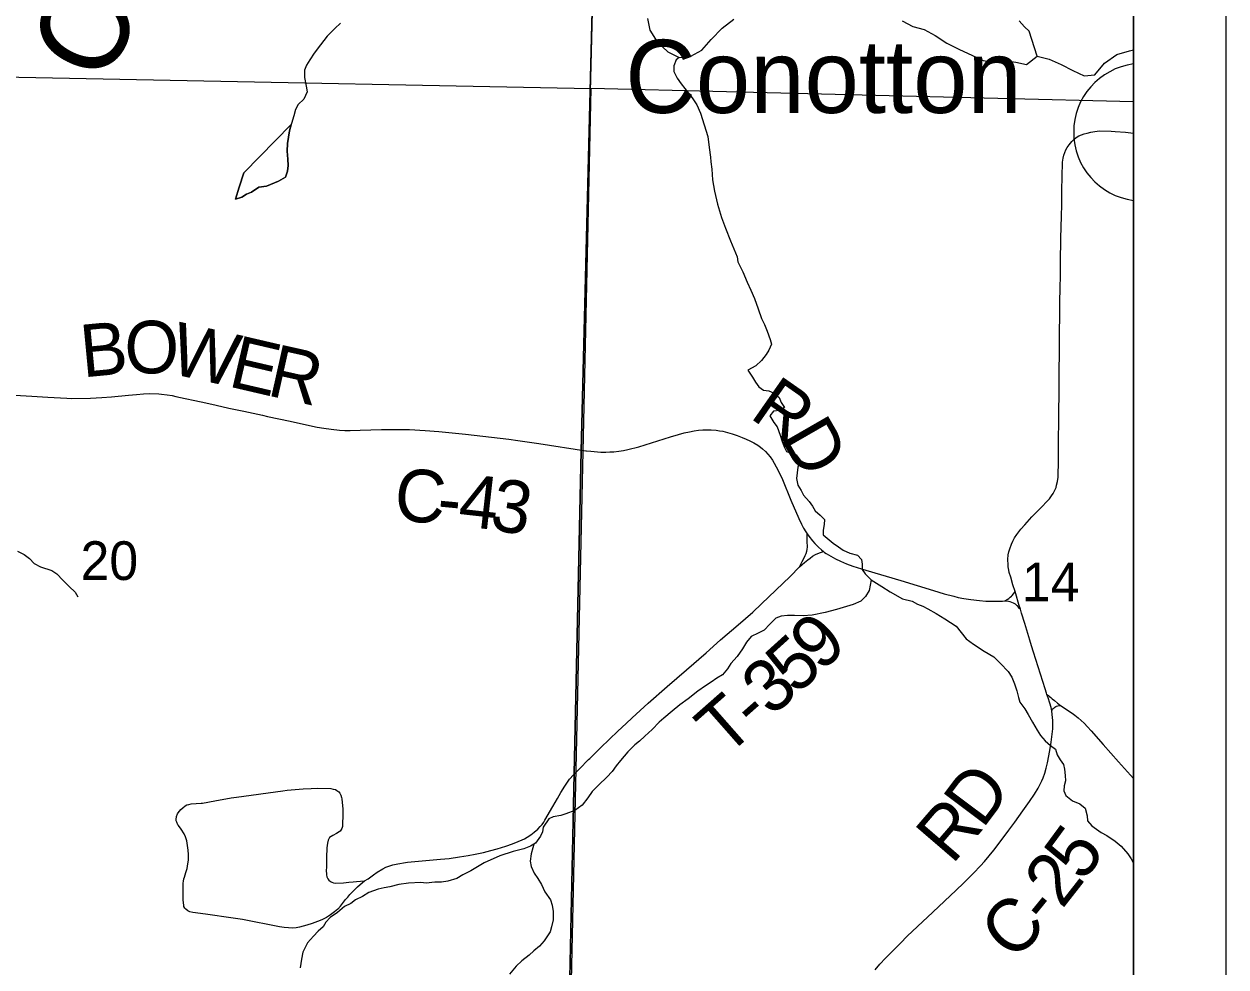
# Model space of a CAD drawing. Extents: x -1.2 to 34, y -8.5 to 22.
# Drawn here: x 7.701 to 9, y 15.729 to 16.749 of the extents above; entities that cross this region are included whole.
import ezdxf

# ---------------------------------------------------------------- set-up
doc = ezdxf.new("R2010")
doc.units = 0
for name, color, linetype in [('GM_X_City_Street', 7, 'Continuous'), ('GM_X_County_Road', 7, 'Continuous'), ('GM_X_County_Road_Text', 7, 'Continuous'), ('GM_X_Major_River', 7, 'Continuous'), ('GM_X_Major_River_Text', 7, 'Continuous'), ('GM_X_Minor_River', 7, 'Continuous'), ('GM_X_Section', 7, 'Continuous'), ('GM_X_Section_Text', 7, 'Continuous'), ('GM_X_Township_Road', 7, 'Continuous'), ('GM_X_Township_Road_Text', 7, 'Continuous'), ('GM_X_Unincorporated_Text', 7, 'Continuous'), ('SH_Cut_Line', 7, 'Continuous'), ('SH_Data', 7, 'Continuous')]:
    doc.layers.add(name, color=color, linetype=linetype)

msp = doc.modelspace()

# ---------------------------------------------------------------- linework, layer by layer
at = {"layer": 'GM_X_City_Street'}
msp.add_line((8.9, 16.5579), (8.9, 16.7054), dxfattribs=at)
msp.add_arc((8.9098, 16.6316), 0.0744, 97.5674, 262.4326, dxfattribs=at)
at = {"layer": 'GM_X_County_Road'}
for points in [[(8.7778, 16.1158), (8.7762, 16.1209), (8.7727, 16.1325), (8.772, 16.135), (8.7697, 16.1424), (8.7673, 16.1505), (8.7658, 16.1556), (8.7652, 16.1582), (8.7646, 16.1616), (8.7644, 16.1639), (8.7642, 16.1697), (8.7646, 16.1748), (8.7652, 16.178), (8.7662, 16.1813), (8.7682, 16.1861), (8.7697, 16.1895), (8.7716, 16.193), (8.774, 16.1966), (8.7783, 16.2026), (8.7826, 16.2072), (8.79, 16.2158), (8.7951, 16.2209), (8.8014, 16.227), (8.806, 16.232), (8.8091, 16.2352), (8.8115, 16.2385), (8.8131, 16.2409), (8.8148, 16.2439), (8.8164, 16.2475), (8.817, 16.25), (8.818, 16.2541), (8.8185, 16.2587), (8.8187, 16.2645), (8.8189, 16.2712), (8.819, 16.3012), (8.8193, 16.3172), (8.8194, 16.3236), (8.8195, 16.3338), (8.8196, 16.3445), (8.8197, 16.3555), (8.8198, 16.3791), (8.82, 16.3872), (8.8201, 16.3992), (8.8202, 16.4178), (8.8203, 16.4304), (8.8206, 16.4507), (8.8208, 16.4603), (8.821, 16.4792), (8.8211, 16.4907), (8.8215, 16.5171), (8.8222, 16.5407), (8.8225, 16.553), (8.8227, 16.5689), (8.8229, 16.5833), (8.8234, 16.5991), (8.8239, 16.6035), (8.8249, 16.6067), (8.8259, 16.6097), (8.827, 16.6125), (8.8285, 16.615), (8.8306, 16.618), (8.8335, 16.6216), (8.8355, 16.6237), (8.838, 16.6258), (8.8409, 16.6275), (8.8437, 16.6288), (8.8469, 16.6298), (8.85, 16.6306), (8.8541, 16.6316), (8.8584, 16.6323), (8.8634, 16.6329), (8.8759, 16.6327), (8.8804, 16.6325), (8.8915, 16.6317), (8.9, 16.6307)], [(7.6908, 16.3472), (7.7094, 16.3463), (7.7266, 16.3453), (7.7469, 16.344), (7.7526, 16.3438), (7.7728, 16.344), (7.7848, 16.3447), (7.7955, 16.3455), (7.8137, 16.3472), (7.8223, 16.3481), (7.8301, 16.3487), (7.8364, 16.349), (7.8465, 16.3488), (7.8495, 16.3485), (7.8554, 16.3478), (7.8608, 16.3468), (7.8649, 16.346), (7.8751, 16.3438), (7.8853, 16.3416), (7.8973, 16.3389), (7.9085, 16.3365), (7.9223, 16.3334), (7.9383, 16.33), (7.9586, 16.3256), (7.9639, 16.3244), (7.9884, 16.3191), (8.0092, 16.3145), (8.0175, 16.3128), (8.0248, 16.3115), (8.0329, 16.3104), (8.0418, 16.3095), (8.0475, 16.3091), (8.0533, 16.309), (8.0643, 16.3093), (8.0757, 16.3097), (8.0872, 16.3101), (8.0969, 16.3103), (8.1084, 16.3103), (8.1174, 16.3101), (8.1344, 16.3091), (8.149, 16.308), (8.1637, 16.3066), (8.1781, 16.3051), (8.2248, 16.2997), (8.2344, 16.2984), (8.2571, 16.295), (8.3079, 16.2872), (8.3088, 16.2871)], [(8.3088, 16.2871), (8.3133, 16.2866), (8.3242, 16.2858), (8.3297, 16.2857), (8.334, 16.2859), (8.3385, 16.2862), (8.3439, 16.2867), (8.3487, 16.2876), (8.3534, 16.2887), (8.3652, 16.2915), (8.3792, 16.2956), (8.3997, 16.3023), (8.4084, 16.3049), (8.4145, 16.3065), (8.42, 16.3078), (8.4253, 16.3086), (8.4298, 16.3093), (8.4345, 16.3097), (8.4391, 16.31), (8.4435, 16.3098), (8.4488, 16.3094), (8.4526, 16.3088), (8.4563, 16.3083), (8.4611, 16.3071), (8.4664, 16.3055), (8.4717, 16.3036), (8.4769, 16.3017), (8.4815, 16.2997), (8.4854, 16.2978), (8.4898, 16.2956), (8.4939, 16.2932), (8.4969, 16.291), (8.4989, 16.2893), (8.5021, 16.2865), (8.5049, 16.2835), (8.5074, 16.2805), (8.5097, 16.2772), (8.5117, 16.2739), (8.516, 16.266), (8.5206, 16.2561), (8.5298, 16.2339), (8.5383, 16.2138), (8.5411, 16.2078), (8.5433, 16.2036), (8.5459, 16.1995), (8.5473, 16.1975), (8.5491, 16.1949), (8.5532, 16.1897), (8.5557, 16.1868), (8.5594, 16.183), (8.5628, 16.18), (8.5649, 16.1783), (8.5661, 16.1774), (8.5679, 16.1762), (8.5729, 16.1732), (8.5778, 16.1703), (8.5835, 16.1677), (8.59, 16.165), (8.5968, 16.1626), (8.6107, 16.1581), (8.6485, 16.1469), (8.6839, 16.1361), (8.6955, 16.1326), (8.7057, 16.1299), (8.7107, 16.1287), (8.7168, 16.1276), (8.7243, 16.1264), (8.7335, 16.1253), (8.7406, 16.1247), (8.7479, 16.1245), (8.7539, 16.1246), (8.7586, 16.1247), (8.7611, 16.1248)], [(8.7611, 16.1248), (8.7635, 16.1264), (8.7652, 16.1276), (8.7668, 16.1288), (8.7681, 16.13), (8.7689, 16.1309), (8.7702, 16.1324), (8.7713, 16.1341), (8.772, 16.135)], [(8.7611, 16.1248), (8.7648, 16.1246), (8.7662, 16.1244), (8.7683, 16.1237), (8.77, 16.1229), (8.772, 16.1216), (8.7739, 16.1199), (8.7758, 16.1179), (8.7778, 16.1158)], [(8.8065, 16.0238), (8.8061, 16.025), (8.8045, 16.0297), (8.7994, 16.0456), (8.7921, 16.0694), (8.7899, 16.0765), (8.788, 16.0826), (8.7849, 16.0931), (8.7826, 16.1004), (8.7791, 16.1118), (8.7778, 16.1158)], [(8.6208, 15.7262), (8.6259, 15.7321), (8.6319, 15.7386), (8.6394, 15.7461), (8.6483, 15.755), (8.6555, 15.7623), (8.6664, 15.7728), (8.6833, 15.7885), (8.7083, 15.8122), (8.7164, 15.8196), (8.727, 15.8305), (8.7348, 15.8386), (8.7389, 15.8432), (8.7491, 15.8555), (8.7526, 15.86), (8.7652, 15.8769), (8.7717, 15.8858), (8.7805, 15.8978), (8.7878, 15.9082), (8.7929, 15.9159), (8.7969, 15.9223), (8.7986, 15.9254), (8.8011, 15.9304), (8.8025, 15.9338), (8.8042, 15.9388), (8.8057, 15.944), (8.807, 15.9498), (8.8095, 15.9632), (8.8109, 15.9722), (8.8128, 15.9867), (8.813, 15.9895), (8.8128, 15.9955), (8.8121, 16.002), (8.8116, 16.0061), (8.8109, 16.0095), (8.8096, 16.0143), (8.8078, 16.0202), (8.8065, 16.0238)], [(8.8065, 16.0238), (8.8081, 16.0225), (8.8093, 16.0215), (8.8106, 16.0204), (8.8123, 16.019), (8.8146, 16.0171), (8.8178, 16.0145), (8.8213, 16.012), (8.8336, 16.0034), (8.8365, 16.0014), (8.8401, 15.9985), (8.8435, 15.9957), (8.8466, 15.9926), (8.8504, 15.9887), (8.8542, 15.9846), (8.8672, 15.9698), (8.884, 15.951), (8.8937, 15.94), (8.9, 15.9328)], [(8.8116, 16.0061), (8.8126, 16.0077), (8.8133, 16.0086), (8.8142, 16.0094), (8.8151, 16.0101), (8.816, 16.0106), (8.8169, 16.011), (8.8181, 16.0114), (8.8213, 16.012)]]:
    msp.add_lwpolyline(points, dxfattribs=at)
at = {"layer": 'GM_X_Major_River'}
for points in [[(8.3746, 16.7544), (8.3774, 16.7419), (8.3851, 16.7294), (8.3966, 16.7186), (8.4089, 16.7123), (8.4214, 16.7136), (8.4335, 16.7202), (8.4436, 16.7317), (8.4556, 16.744), (8.468, 16.7536)], [(8.6499, 16.752), (8.6614, 16.7457), (8.6739, 16.7425), (8.6858, 16.7361), (8.6984, 16.728), (8.7118, 16.7209), (8.7252, 16.715), (8.7374, 16.7091), (8.7499, 16.707), (8.7632, 16.7086), (8.7727, 16.7072), (8.7845, 16.7047), (8.7958, 16.7136), (8.8088, 16.7107), (8.8217, 16.7048), (8.8343, 16.6981), (8.8469, 16.6926), (8.8583, 16.6935), (8.8688, 16.7061), (8.882, 16.7154), (8.8956, 16.7197), (8.9, 16.7205)]]:
    msp.add_lwpolyline(points, dxfattribs=at)
at = {"layer": 'GM_X_Minor_River'}
for points in [[(8.0428, 16.7493), (8.0368, 16.7438), (8.0283, 16.7353), (8.0212, 16.7261), (8.0145, 16.7169), (8.0097, 16.7099), (8.006, 16.7042), (8.0038, 16.6988), (8.0039, 16.6908), (8.0059, 16.6813), (8.0068, 16.6752), (8.0031, 16.6672), (7.9971, 16.6614), (7.9942, 16.656), (7.9924, 16.6491), (7.9899, 16.6411), (7.9877, 16.6331), (7.9856, 16.6193), (7.9854, 16.6109), (7.9859, 16.6026), (7.9864, 16.5957), (7.9857, 16.5896), (7.9835, 16.5831), (7.976, 16.5788), (7.9628, 16.5733), (7.9545, 16.572), (7.9466, 16.5666), (7.9414, 16.5646), (7.9361, 16.5615), (7.9293, 16.5591), (7.9333, 16.5721), (7.9384, 16.5878), (7.9891, 16.6396)], [(8.7958, 16.7136), (8.7873, 16.7407), (8.7823, 16.7456), (8.7765, 16.752)], [(8.4089, 16.7123), (8.4057, 16.7098), (8.4032, 16.7033), (8.4032, 16.6972), (8.4068, 16.69), (8.411, 16.684), (8.4152, 16.6787), (8.423, 16.6686), (8.428, 16.661), (8.4319, 16.652), (8.4398, 16.627), (8.4415, 16.6152), (8.4428, 16.6045), (8.4433, 16.5996), (8.4441, 16.5916), (8.4451, 16.5802), (8.4471, 16.568), (8.4504, 16.5536), (8.4547, 16.5392), (8.4591, 16.5279), (8.4646, 16.5143), (8.4716, 16.4968), (8.4725, 16.4915), (8.4779, 16.4806), (8.4826, 16.4696), (8.4865, 16.4609), (8.4905, 16.4518), (8.4944, 16.4408), (8.498, 16.4302), (8.5011, 16.4238), (8.5042, 16.4166), (8.5074, 16.4075), (8.5086, 16.4026), (8.506, 16.3961), (8.5031, 16.3911), (8.4979, 16.3849), (8.4919, 16.3791), (8.4832, 16.3744), (8.4883, 16.3669), (8.4914, 16.3612), (8.4952, 16.3563), (8.5002, 16.3526), (8.5059, 16.3519), (8.5109, 16.3497), (8.517, 16.3449), (8.5193, 16.3392), (8.5228, 16.3339), (8.5176, 16.3308), (8.5108, 16.3299), (8.5071, 16.3249), (8.5113, 16.3178), (8.5148, 16.3129), (8.518, 16.3042), (8.5203, 16.2973), (8.5223, 16.2913), (8.525, 16.2864), (8.53, 16.2845), (8.5353, 16.2827), (8.5399, 16.2771), (8.5374, 16.2694), (8.5364, 16.2633), (8.5357, 16.2572), (8.5373, 16.25), (8.5408, 16.2444), (8.5435, 16.2391), (8.5493, 16.2323), (8.5532, 16.2274), (8.5559, 16.2221), (8.5612, 16.2176), (8.5659, 16.2128), (8.5656, 16.2074), (8.5645, 16.2013), (8.5646, 16.1964), (8.5753, 16.1874), (8.5811, 16.1833), (8.5864, 16.1796), (8.5933, 16.1766), (8.6016, 16.1745), (8.6062, 16.1696), (8.6067, 16.1647), (8.6068, 16.1589), (8.6099, 16.154), (8.6164, 16.1477), (8.6282, 16.1406), (8.637, 16.1347), (8.6504, 16.1273), (8.6607, 16.1247), (8.6664, 16.1214), (8.6725, 16.1192), (8.6778, 16.1163), (8.6866, 16.1114), (8.6961, 16.1055), (8.7084, 16.0977), (8.7192, 16.0838), (8.7272, 16.0782), (8.7387, 16.0707), (8.749, 16.0644), (8.7563, 16.0573), (8.7647, 16.0487), (8.7686, 16.0426), (8.7714, 16.0351)], [(7.9293, 16.5591), (7.9361, 16.5615), (7.9414, 16.5646), (7.9466, 16.5666), (7.9545, 16.572), (7.9628, 16.5733), (7.976, 16.5788), (7.9835, 16.5831), (7.9857, 16.5896), (7.9864, 16.5957), (7.9859, 16.6026), (7.9854, 16.6109), (7.9856, 16.6193), (7.9877, 16.6331), (7.9896, 16.64)], [(7.9896, 16.64), (7.9384, 16.5878), (7.9333, 16.5721), (7.9293, 16.5591)], [(7.6937, 16.1786), (7.7009, 16.1749), (7.7067, 16.1708), (7.7117, 16.1652), (7.7185, 16.1619), (7.7307, 16.1579), (7.7364, 16.1541), (7.7426, 16.1474), (7.7495, 16.1406), (7.756, 16.1343), (7.7591, 16.1294)], [(8.6165, 16.1476), (8.6143, 16.1362), (8.6102, 16.1297), (8.6054, 16.1247), (8.5971, 16.1211), (8.5899, 16.1187), (8.579, 16.1155), (8.5666, 16.1123), (8.5526, 16.1094), (8.5431, 16.1089), (8.5337, 16.1091), (8.5261, 16.109), (8.5193, 16.1085), (8.5136, 16.1061), (8.5069, 16.0996), (8.501, 16.0934), (8.4942, 16.0899), (8.4867, 16.0863), (8.4818, 16.0802), (8.4774, 16.0732), (8.4718, 16.0648), (8.4648, 16.0571), (8.4611, 16.0513), (8.4558, 16.0451), (8.4495, 16.0412), (8.4435, 16.0369), (8.4375, 16.033), (8.4292, 16.0272), (8.4187, 16.019), (8.4098, 16.0124), (8.4015, 16.0058), (8.3922, 15.9981), (8.3873, 15.9938), (8.3798, 15.9857), (8.372, 15.9787), (8.366, 15.9733), (8.3612, 15.9694), (8.3533, 15.9617), (8.3455, 15.9525), (8.341, 15.9467), (8.3366, 15.9405), (8.3306, 15.9343), (8.322, 15.9262), (8.3149, 15.9189), (8.3101, 15.912), (8.3042, 15.9042), (8.2963, 15.8984), (8.2865, 15.8948), (8.2809, 15.8929), (8.2729, 15.8916), (8.268, 15.8892), (8.2621, 15.8804), (8.2611, 15.8754), (8.2589, 15.8704), (8.2537, 15.8631), (8.2484, 15.8596), (8.2409, 15.8568), (8.2296, 15.854), (8.2152, 15.8492), (8.1983, 15.8417), (8.1837, 15.8331), (8.175, 15.8288), (8.1686, 15.8249), (8.1588, 15.8221), (8.152, 15.8209), (8.1449, 15.8207), (8.1354, 15.8198), (8.1297, 15.8205), (8.1165, 15.8196), (8.1059, 15.8183), (8.0961, 15.8158), (8.09, 15.8146), (8.0836, 15.8133), (8.0735, 15.8098), (8.0667, 15.8055), (8.0592, 15.8019), (8.0539, 15.7977), (8.0472, 15.7945), (8.0397, 15.7879), (8.0318, 15.7825), (8.027, 15.7775), (8.024, 15.7725), (8.0188, 15.7678), (8.0136, 15.7624), (8.0072, 15.7551), (8.0021, 15.7451), (8.0007, 15.7375), (7.9993, 15.7283)], [(8.7714, 16.0351), (8.7738, 16.0275), (8.7758, 16.0203), (8.7773, 16.0154), (8.7827, 16.0082), (8.7862, 16.0022), (8.7909, 15.9939), (8.796, 15.9852), (8.7994, 15.9795), (8.8045, 15.9735), (8.8102, 15.9687), (8.8159, 15.9646), (8.8175, 15.9585), (8.8207, 15.9532), (8.8245, 15.948), (8.8253, 15.943), (8.8262, 15.9362), (8.8267, 15.9305), (8.8252, 15.9251), (8.8246, 15.9194), (8.8269, 15.9145), (8.8342, 15.9089), (8.8422, 15.9056), (8.8479, 15.9007), (8.8499, 15.8924), (8.8504, 15.8871), (8.855, 15.8818), (8.865, 15.8747), (8.8711, 15.8714), (8.8802, 15.8651), (8.8868, 15.8598), (8.8941, 15.8516), (8.8976, 15.8459), (8.9, 15.8414)], [(8.2519, 15.862), (8.2507, 15.8578), (8.2489, 15.8513), (8.2479, 15.8436), (8.2491, 15.8376), (8.2522, 15.8304), (8.2561, 15.8247), (8.26, 15.8183), (8.2639, 15.8104), (8.2697, 15.8017), (8.2717, 15.796), (8.2729, 15.7892), (8.2727, 15.7801), (8.2709, 15.7724), (8.2694, 15.7671), (8.2631, 15.7575), (8.2579, 15.7517), (8.2519, 15.7466), (8.2467, 15.742), (8.2389, 15.7358), (8.2329, 15.73), (8.2254, 15.7215)]]:
    msp.add_lwpolyline(points, dxfattribs=at)
at = {"layer": 'GM_X_Section'}
for points in [[(7.2949, 16.6991), (8.3136, 16.6787), (8.2912, 15.6653), (7.2776, 15.674)], [(8.9, 15.6494), (8.9, 16.6645), (8.3136, 16.6787), (8.2912, 15.6653)]]:
    msp.add_lwpolyline(points, close=True, dxfattribs=at)
at = {"layer": 'GM_X_Township_Road'}
for points in [[(8.5392, 16.1616), (8.5401, 16.1639), (8.5418, 16.1674), (8.5436, 16.1708), (8.5451, 16.174), (8.5461, 16.1761), (8.547, 16.1785), (8.5474, 16.1804), (8.5477, 16.1833), (8.5474, 16.1891), (8.5472, 16.1926), (8.5473, 16.1975)], [(8.3109, 15.9533), (8.3123, 15.9547), (8.3238, 15.966), (8.3336, 15.9754), (8.3427, 15.9841), (8.3517, 15.9925), (8.3583, 15.9985), (8.3756, 16.0142), (8.3961, 16.0322), (8.4168, 16.0503), (8.438, 16.0687), (8.4536, 16.0827), (8.4729, 16.099), (8.4885, 16.1128), (8.498, 16.1218), (8.529, 16.1514), (8.5392, 16.1616), (8.5419, 16.1643), (8.5443, 16.1663), (8.5479, 16.1692), (8.5504, 16.1712), (8.5532, 16.1731), (8.5564, 16.175), (8.5587, 16.1761), (8.5617, 16.1773), (8.5649, 16.1783)], [(8.2982, 15.9405), (8.3041, 15.9464), (8.3081, 15.9505), (8.3109, 15.9533)], [(8.043, 15.7949), (8.046, 15.7991), (8.0484, 15.802), (8.0507, 15.8047), (8.0531, 15.8074), (8.0567, 15.8111), (8.0614, 15.8158), (8.0641, 15.8183), (8.0689, 15.8222), (8.0726, 15.8246), (8.0787, 15.8289), (8.0826, 15.8315), (8.0888, 15.8352), (8.092, 15.8369), (8.0962, 15.8385), (8.0993, 15.8395), (8.1048, 15.8408), (8.1131, 15.8421), (8.1152, 15.8424), (8.1508, 15.8456), (8.1604, 15.8466), (8.1716, 15.8481), (8.1809, 15.8496), (8.1886, 15.8511), (8.1973, 15.853), (8.2053, 15.855), (8.2124, 15.857), (8.2215, 15.8599), (8.2287, 15.8624), (8.2348, 15.8647), (8.2393, 15.8667), (8.2417, 15.8678), (8.2447, 15.8695), (8.2487, 15.8721), (8.2523, 15.8749), (8.2562, 15.8783), (8.2588, 15.8809), (8.2608, 15.8833), (8.2625, 15.8857), (8.2638, 15.8877), (8.2724, 15.9026), (8.2773, 15.9114), (8.2809, 15.9176), (8.2854, 15.9247), (8.2883, 15.9288), (8.2905, 15.9322), (8.2946, 15.9368), (8.2982, 15.9405)], [(8.043, 15.7949), (8.04, 15.7918), (8.0364, 15.7889), (8.0322, 15.7857), (8.0279, 15.7827), (8.0226, 15.7802), (8.0179, 15.7783), (8.0122, 15.7762), (8.0066, 15.7745), (8.0025, 15.7731), (7.9984, 15.7722), (7.9948, 15.7715), (7.9914, 15.7712), (7.982, 15.7719), (7.9771, 15.7726), (7.9369, 15.7804), (7.9269, 15.782), (7.897, 15.7863), (7.8831, 15.7882), (7.88, 15.7889), (7.8777, 15.79), (7.8758, 15.7915), (7.8746, 15.7928), (7.8736, 15.7947), (7.8734, 15.7963), (7.8731, 15.7982), (7.8729, 15.8022), (7.8728, 15.8081), (7.8729, 15.8199), (7.8732, 15.822), (7.8736, 15.8243), (7.8742, 15.8262), (7.8757, 15.8312), (7.877, 15.8357), (7.8779, 15.8405), (7.8785, 15.8448), (7.8786, 15.8506), (7.8783, 15.8555), (7.8769, 15.8654), (7.8755, 15.87), (7.874, 15.8731), (7.8708, 15.878), (7.8678, 15.882), (7.8672, 15.883), (7.8658, 15.8858), (7.8654, 15.8871), (7.8652, 15.8887), (7.8655, 15.8918), (7.8667, 15.8947), (7.8674, 15.8959), (7.8688, 15.8977), (7.8703, 15.8994), (7.8723, 15.9012), (7.8749, 15.9032), (7.8767, 15.9044), (7.8791, 15.9049), (7.8813, 15.9054), (7.8869, 15.9058), (7.8922, 15.9062), (7.8937, 15.9064), (7.9069, 15.9088), (7.9247, 15.912), (7.9304, 15.9128), (7.9806, 15.9197), (7.9851, 15.9202), (8.0025, 15.9217), (8.0112, 15.9221), (8.0179, 15.9223), (8.0325, 15.922), (8.035, 15.9215), (8.0373, 15.9209), (8.039, 15.9201), (8.04, 15.9193), (8.0409, 15.9185), (8.0421, 15.917), (8.0431, 15.915), (8.0441, 15.9123), (8.0443, 15.911), (8.0453, 15.8999), (8.0455, 15.8957), (8.0451, 15.8809), (8.0443, 15.8788), (8.0433, 15.877), (8.0424, 15.8759), (8.0415, 15.8751), (8.0386, 15.8734), (8.0345, 15.8713), (8.0309, 15.8691), (8.0294, 15.8661), (8.0288, 15.8631), (8.0282, 15.8578), (8.0279, 15.8476), (8.0276, 15.838), (8.0275, 15.8323), (8.0276, 15.8304), (8.0276, 15.8286), (8.0282, 15.8266), (8.0293, 15.8243), (8.0303, 15.823), (8.0319, 15.8217), (8.0334, 15.8209), (8.0353, 15.8202), (8.0376, 15.8199), (8.0461, 15.8202), (8.0519, 15.8208), (8.0566, 15.8213), (8.0602, 15.8215), (8.0689, 15.8222)]]:
    msp.add_lwpolyline(points, dxfattribs=at)
at = {"layer": 'GM_X_Unincorporated_Text'}
for p, q in [((8.3029, 16.2873), (8.3265, 17.2224)), ((8.2955, 15.9378), (8.3029, 16.2873)), ((8.2794, 15.1757), (8.2955, 15.9378))]:
    msp.add_line(p, q, dxfattribs=at)
msp.add_lwpolyline([(8.2551, 14.1), (8.9, 14.1), (8.9, 17.6758), (8.3326, 17.6871), (8.3265, 17.2224), (8.3029, 16.2873), (8.2955, 15.9378), (8.2794, 15.1757), (8.2772, 15.0742)], close=True, dxfattribs=at)
at = {"layer": 'SH_Cut_Line'}
msp.add_lwpolyline([(2.3586, 14.1), (8.9, 14.1), (8.9, 17.6758), (8.3326, 17.6871), (7.9782, 17.6941), (7.8111, 17.6977), (7.3722, 17.707), (7.1254, 17.7122), (6.7322, 17.7204), (6.6751, 17.7216), (6.665, 17.7216)], dxfattribs=at)
at = {"layer": 'SH_Data'}
for p, q in [((9, 21), (9, 14)), ((9, 21), (9, 14)), ((8.9, 20.9), (8.9, 14.1)), ((8.9, 20.9), (8.9, 14.1))]:
    msp.add_line(p, q, dxfattribs=at)

# ---------------------------------------------------------------- texts
at = {"layer": 'GM_X_County_Road_Text'}
for s, rotation, p in [('B', 5.445, (7.7643, 16.3664)), ('O', 0.1785, (7.8094, 16.3708)), ('W', 347.5603, (7.8561, 16.3713)), ('E', 346.8836, (7.9202, 16.3571)), ('R', 347.3633, (7.9621, 16.3474)), ('R', 325.0953, (8.4838, 16.3236)), ('D', 299.931, (8.5176, 16.3017)), ('C', 354.9232, (8.0995, 16.2125)), ('4', 353.5334, (8.1688, 16.2062)), ('3', 350.4855, (8.2028, 16.2024)), ('-', 354.5978, (8.1459, 16.2084)), ('D', 53.1804, (8.7369, 15.8775)), ('R', 49.3233, (8.704, 15.8389)), ('5', 53.6791, (8.8455, 15.82)), ('2', 51.9858, (8.8228, 15.7909)), ('C', 44.448, (8.7693, 15.7341)), ('-', 50.7452, (8.8072, 15.7718))]:
    msp.add_text(s, height=0.0568, rotation=rotation, dxfattribs=at).set_placement(p)
at = {"layer": 'GM_X_Major_River_Text'}
msp.add_text('Conotton', height=0.09472, rotation=63.5646, dxfattribs=at).set_placement((7.7875, 16.6807))
at = {"layer": 'GM_X_Section_Text'}
for s, p in [('20', (7.7619, 16.1475)), ('14', (8.7794, 16.1245))]:
    msp.add_text(s, height=0.04186, rotation=0, dxfattribs=at).set_placement(p)
at = {"layer": 'GM_X_Township_Road_Text'}
for s, rotation, p in [('9', 43.5523, (8.5624, 16.0469)), ('5', 42.0841, (8.5353, 16.0224)), ('3', 41.6112, (8.5087, 15.9988)), ('T', 41.3641, (8.4592, 15.9551)), ('-', 41.4024, (8.4911, 15.9832))]:
    msp.add_text(s, height=0.0568, rotation=rotation, dxfattribs=at).set_placement(p)
at = {"layer": 'GM_X_Unincorporated_Text'}
msp.add_text('Conotton', height=0.07898, rotation=0, dxfattribs=at).set_placement((8.3507, 16.6524))

doc.saveas('drawing.dxf')
